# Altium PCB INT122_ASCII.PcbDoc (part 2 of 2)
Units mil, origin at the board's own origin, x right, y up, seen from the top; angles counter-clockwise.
Board outline 4500 x 3260 mil, 4 copper layers (Top Layer, GND Layer, VCC Layer, Bottom Layer), stack 61.6 mil thick; 94 components, 30 nets, 233 pads, 39 vias.
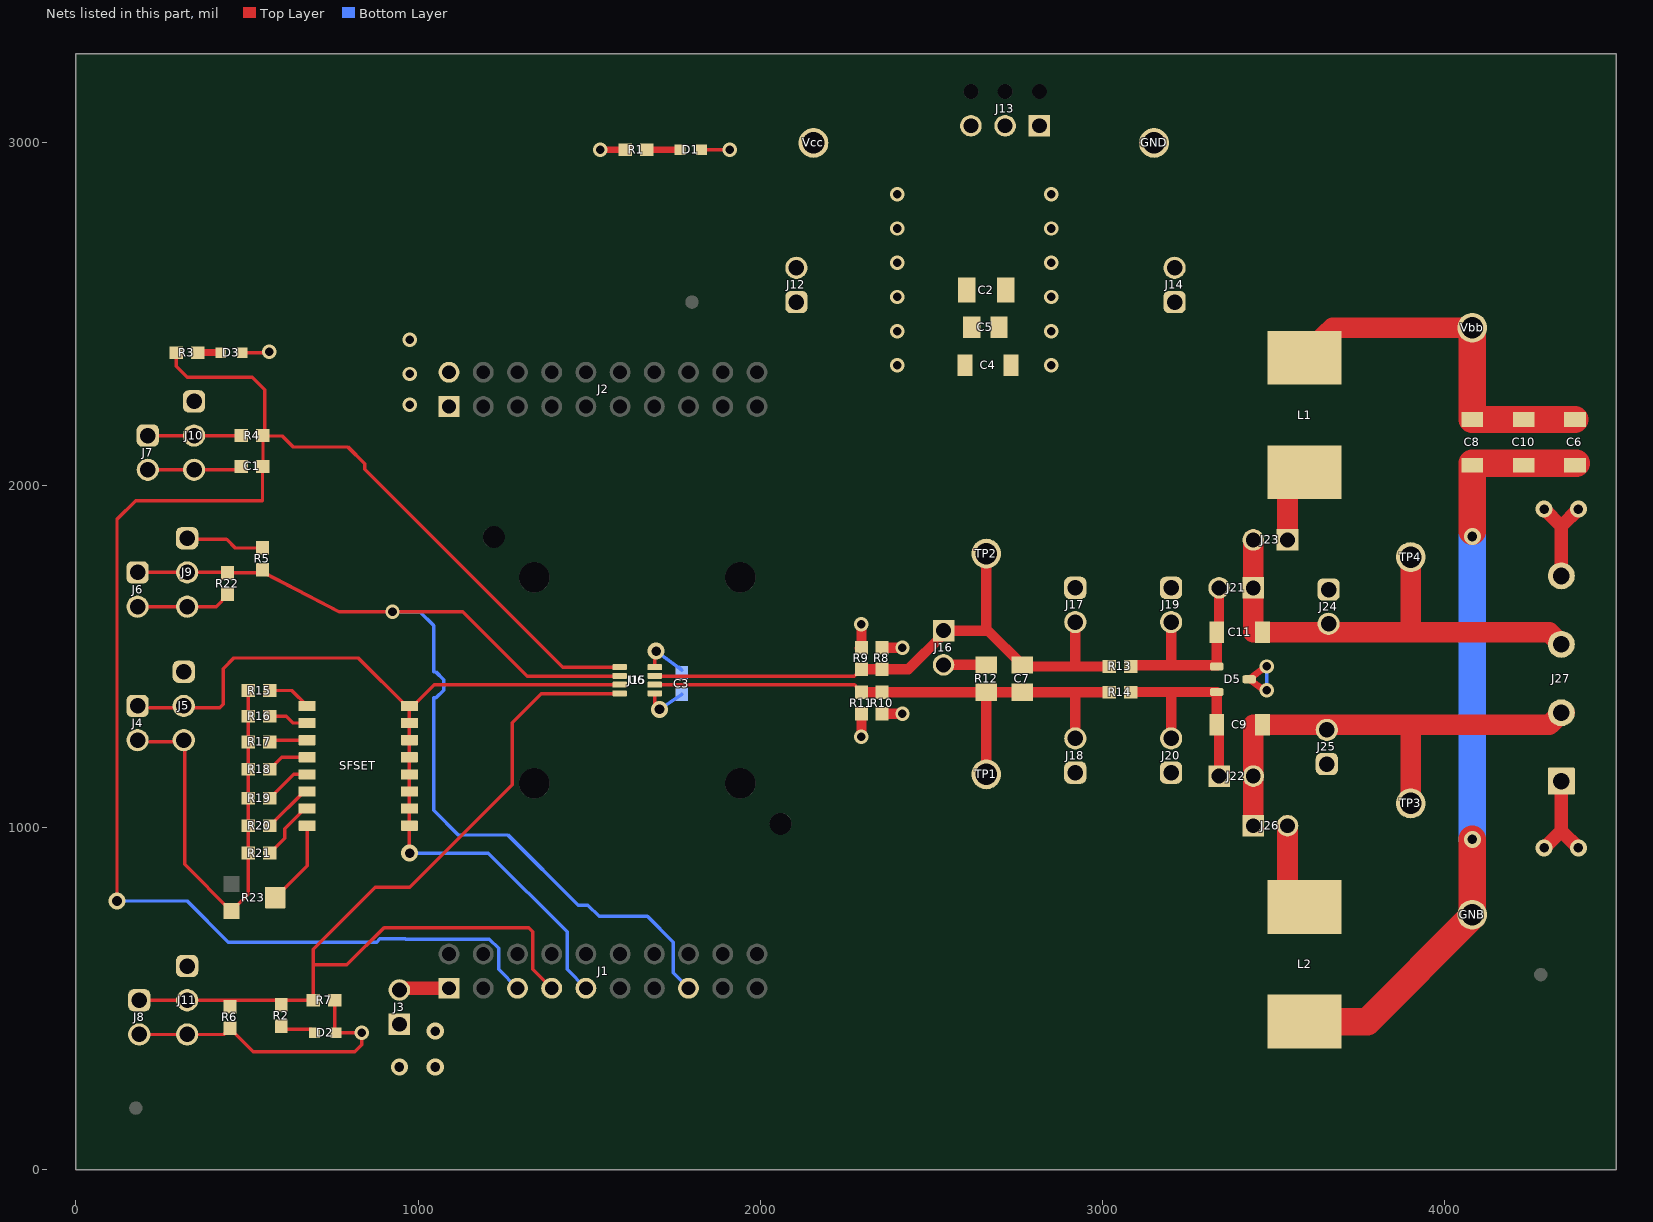
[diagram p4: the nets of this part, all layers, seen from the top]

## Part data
C1: library part CMP-0006767-4, "CAP, CERM, 15 pF, 50 V, +/- 5%, C0G/NP0, 0603"
C2: library part CMP-0008509-2, "CAP, CERM, 1 uF, 25 V, +/- 10%, X7R, 1206"
C3: library part CMP-0085846-1, "CAP, CERM, 0.1 µF, 6.3 V,+/- 10%, X5R, 0603"
C4: library part CMP-0008705-2, "CAP, CERM, 10 uF, 35 V, +/- 10%, X7R, 1206"
C5: library part CMP-0078699-1, "CAP, CERM, 47 µF, 10 V,+/- 20%, X5R, 0805"
C6: library part CMP-0008656-2, "CAP, CERM, 47 uF, 25 V, +/- 20%, X5R, 1206_190"
C7: library part CMP-0007567-2, "CAP, CERM, 0.1 uF, 25 V, +/- 10%, X7R, 0805"
C8 C9 C11: library part CMP-0008779-2, "CAP, CERM, 1 uF, 100 V, +/- 10%, X7R, AEC-Q200 Grade 1, 1206"
C10: library part CMP-0008802-2, "CAP, CERM, 10 uF, 50 V, +/- 10%, X7R, 1206"
D1: library part CMP-0002946-3, "LED, Blue, SMD"
D2: library part CMP-0002905-2, "LED, Green, SMD"
D3: library part CMP-0002947-3, "LED, Red, SMD"
D5: library part CMP-0005918-3, "Diode, TVS, Bi, 12 V, 25.9 Vc, SOT-23"
FID1 FID2 FID3: library part CMP-0077181-1, "Fiducial mark.  There is nothing to buy or mount."
GNB GND: library part CMP-0055148-1, "Test Point, Multipurpose, Black, TH"
H1 H2 H3 H4: library part CMP-0003620-1, "Bumpon, Hemisphere, 0.44 X 0.20, Clear"
J1 J2: library part CMP-0055675-1, "Receptacle, 2.54mm, 10x2, Gold, TH"
J3 J16 J21 J22 J23 J26: library part CMP-0075197-1, "Header, 2.54mm, 2x1, TH"
J4 J6 J7 J8 J12 J14 J17 J18 J19 J20 J24 J25: library part CMP-0054794-2, "Header, 2.54 mm, 2x1, Gold, TH"
J5 J9 J10 J11: library part CMP-0054796-2, "Header, 2.54 mm, 3x1, Gold, TH"
J13: library part CMP-0055500-1, "Terminal Block, 3x1, 2.54 mm, TH"
J15: library part CMP-0088168-1, "CUSTOM SOCKET FOR 1.6X2.9X1.1mm DEVICE, DDF PACKAGE, 0.65mm PITCH, HIGH SPEED SPRING PROBES POGO-1300"
J27: library part CMP-0074939-1, "Terminal Block, 5.08 mm, 4x1, Brass, TH"
L1 L2: library part CMP-0061931-2, "Inductor, Shielded Drum Core, Ferrite, 120 uH, 1.9 A, 0.18 ohm, SMD"
Logo1: library part CMP-0074838-1, "Texas Instrument Corporate Signature"
Logo2: library part CMP-0074844-1
Logo3: library part CMP-0074847-1, "FCC_disclaimer"
Logo4: library part CMP-0074769-1
R1 R2 R3: library part CMP-0025729-4, "RES, 1.0 k, 5%, 0.1 W, AEC-Q200 Grade 0, 0603"
R4 R13 R14: library part CMP-0081973-1, "RES, 0, 0%, 0.25 W, AEC-Q200 Grade 0, 0603"
R5 R7: library part CMP-0025945-3, "RES, 10 k, 5%, 0.1 W, 0603"
R6 R22: library part CMP-0082504-1, "RES, 50, 2%, 3.9 W, 0603"
R8 R11: library part CMP-0025890-5, "RES, 15 k, 5%, 0.1 W, 0603"
R9 R10 R18: library part CMP-0022777-5, "RES, 12.4 k, 1%, 0.1 W, 0603"
R12: library part CMP-0020795-2, "RES, 120, 5%, 0.5 W, 0805"
R15: library part CMP-0022689-3, "RES, 1.50 k, 1%, 0.1 W, 0603"
R16: library part CMP-0022453-4, "RES, 4.42 k, 1%, 0.1 W, AEC-Q200 Grade 0, 0603"
R17: library part CMP-0022666-4, "RES, 9.31 k, 1%, 0.1 W, AEC-Q200 Grade 0, 0603"
R19: library part CMP-0022860-5, "RES, 19.1 k, 1%, 0.1 W, 0603"
R20: library part CMP-0023142-5, "RES, 49.9 k, 1%, 0.1 W, 0603"
R21: library part CMP-0022593-4, "RES, 76.8 k, 1%, 0.1 W, AEC-Q200 Grade 0, 0603"
R23: library part CMP-0065392-2, "TRIMMER 10K OHM 0.1W"
SFSET: library part CMP-0065297-1, "Switch, 8SPST, 0.025 A, 24 VDC, SMD"
SH-J1 SH-J2: library part CMP-0078738-1, "Single Operation 2.54mm Pitch Open Top Jumper Socket"
TP1 TP2 TP3 TP4: library part CMP-0055149-1, "Test Point, Multipurpose, White, TH"
U6: library part CMP-0088703-2, "RS-485 Transceiver with OOK Modulation for Power Line Communication"
Vbb Vcc: library part CMP-0055147-1, "Test Point, Multipurpose, Red, TH"
ZZ1: library part CMP-0003616-3
ZZ2: library part CMP-0077236-1
ZZ3: library part CMP-0077237-1
ZZ4: library part CMP-0077238-1

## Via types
v1: diameter 42, hole 25, Top Layer to Bottom Layer, 26 vias
v2: diameter 50, hole 28, Top Layer to Bottom Layer, 13 vias

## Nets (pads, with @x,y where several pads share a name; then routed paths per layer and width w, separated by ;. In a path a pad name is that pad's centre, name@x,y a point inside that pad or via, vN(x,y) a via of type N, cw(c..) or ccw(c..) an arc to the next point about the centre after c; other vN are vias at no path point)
A: C7.2 J15.6 J18.2 R10.1 R11.2 R12.1 R14.1 TP1.1 U6.6 | length 1689.3
  Top Layer w10: J15.6@1691,1416.3 2274.76,1416.3 R11.2@2283.07,1407.55
  Top Layer w30: R11.2@2295,1395 R10.1@2355,1395 R12.1@2660,1395 ; TP1.1@2660,1155 R12.1@2660,1395 ; C7.2@2760,1395 R12.1@2660,1395 ; C7.2@2765,1395 2920,1395 ; J18.2@2920,1260 2920,1395 ; R14.1@3018.5,1395 2920,1395
A2: C9.2 D5.2 J20.2 J22.1 R14.2 | length 649.3
  Top Layer w10: R14.2@3081.5,1395 R14.2@3081.95,1395.46 ; J22.1@3331.06,1158.94 J22.1@3340,1150
  Top Layer w30: R14.2@3081.95,1395.46 3200,1395.46 ; J20.2@3200,1260 3200,1395.46 ; C9.2@3331.06,1300.3 3340,1291.36 J22.1@3340,1150 ; C9.2@3333.32,1300.3 D5.2@3333.32,1395.46 3200,1395.46
A_LC: C9.1 J22.2 J25.2 J26.1 J27.2 TP3.1 | length 1449.7
  Top Layer w40: J27.2@4340,1335 J27.2@4360,1335
  Top Layer w60: J26.1@3440,1005 J22.2@3440,1150 3440,1300.3 C9.1@3464.92,1300.3 ; C9.1@3475.22,1300.3 3900,1300.3 ; TP3.1@3900,1070 3900,1300.3 ; J27.2@4340,1335 4305.3,1300.3 3900,1300.3
B: C7.1 J15.7 J16.1 J17.2 R8.1 R9.2 R13.1 TP2.1 U6.7 | length 1781.6
  Top Layer w10: J15.7@1691,1441.9 2274.7,1441.9 R9.2@2295,1462.2
  Top Layer w30: R9.2@2295,1462.2 R8.1@2355,1462.2 2432.2,1462.2 2535,1565 J16.1@2535,1575 2665,1575 C7.1@2765,1475 2769.74,1470.26 2920,1470.26 ; 2660,1580 TP2.1@2660,1800 ; J17.2@2920,1600 2920,1470.26 ; R13.1@3018.5,1470.26 2920,1470.26
B2: C11.2 D5.1 J19.2 J21.2 R13.2 | length 607.6
  Top Layer w30: R13.2@3081.94,1474 D5.1@3335,1474 ; 3200,1475 J19.2@3200,1604.74 ; D5.1@3333.32,1478 C11.2@3333.32,1570.3 3340,1576.98 J21.2@3340,1700
B_LC: C11.1 J21.1 J23.2 J24.2 J27.3 TP4.1 | length 1388.8
  Top Layer w60: J23.2@3440,1840 J21.1@3440,1700 3440,1570.3 C11.1@3466.85,1570.3 ; C11.1@3481.55,1570.3 3899.87,1570.3 ; TP4.1@3899.87,1789.5 3899.87,1570.3 ; J27.3@4340,1535 4304.7,1570.3 3899.87,1570.3
D: J1.7 J8.1 J11.2 J15.4 R2.1 R6.2 R7.2 U6.4 | length 2813.5
  Top Layer w10: J8.1@215,495 315,495 565,495 R7.2@690,495 ; R7.2@693.5,495 693.5,598.5 ; J1.7@1390,530 1335,585 1335,695 1322.99,707.01 900,707.01 791.5,598.5 693.5,598.5 ; J15.4@1589,1390.7 1360,1390.7 1275,1305.7 1275,1125 975,825 875,825 693.5,643.5 693.5,598.5
F_SET: J1.9 J4.1 J5.2 J15.3 SFSET.9 SFSET.10 SFSET.11 SFSET.12 SFSET.13 SFSET.14 SFSET.15 SFSET.16 U6.3 | length 2740.8
  Top Layer w10: 215,1350 315,1350 420,1350 430,1360 430,1463.93 461.07,1495 825,1495 965,1355 SFSET.16@974.41,1355 ; v2@974.41,935.59 SFSET.9@974.41,1005 SFSET.10@974.41,1055 SFSET.11@974.41,1105 SFSET.12@974.41,1155 SFSET.13@974.41,1205 SFSET.14@974.41,1255 SFSET.15@974.41,1305 SFSET.16@974.41,1355 ; J15.3@1589,1416.3 1046.3,1416.3 985,1355 SFSET.16@974.41,1355
  Bottom Layer w10: v2(975,925) 1205,925 1435,695 1435,585 J1.9@1490,530
GND_BRD: C1.2 C2.2 C3.1 C4.2 C5.1 D1.1 D2.1 D3.1 D5.3 GND.1 J2.1 J2.2 J4.2 J5.3 J6.2 J7.2 J8.2 J9.3 J10.3 J11.3 J13.1 J13.2 J14.1 J14.2 J15.5 J17.1 J18.1 J19.1 J20.1 J24.1 J25.1 J27.1 R6.1 R7.1 R9.1 R11.1 R15.1 R16.1 R17.1 R18.1 R19.1 R20.1 R21.1 R22.1 R23.3 U6.5 | length 3640.2
  Top Layer w10: J6.2@175,1645 320,1645 409.43,1645 R22.1@442.5,1678.07 ; J8.2@215,395 315,395 431.5,395 R6.1@450,413.5 518.5,345 815,345 835,365 v1(835,400) D2.1@760.2,400 ; 215,1250 315,1250 317.5,1247.5 317.5,892.26 R23.3@454.13,755.63 503.5,805 R21.1@503.5,925 R20.1@503.5,1005 R19.1@503.5,1085 R18.1@503.5,1170 R17.1@503.5,1250 R16.1@503.5,1325 R15.1@503.5,1400 ; J7.2@225,2045 325,2045 C1.2@480.55,2045 ; D3.1@485.94,2387.2 562.2,2387.2 v1(565,2390) ; D2.1@756.5,403.7 R7.1@756.5,495 ; J15.5@1691,1390.7 1691,1359 v2(1705,1345) ; D1.1@1827.99,2980 v1(1910,2980) ; v1@3472.17,1400.3 v1(3479.92,1400.3) ; v1@3477.05,1470.3 v1(3479.92,1470.3)
  Top Layer w20: R9.1@2285,1523.7 R9.1@2295,1533.7 ; v1@3472.17,1400.3 D5.3@3427.81,1432.86 v1@3477.05,1470.3
  Top Layer w30: v1(2295,1265) R11.1@2295,1332.01 ; R9.1@2295,1533.7 v1@2295,1583.7
  Top Layer w40: v2(4290,940) 4340,990 ; J27.1@4350,1125 J27.1@4340,1135 4340,990 ; v2(4390,940) 4340,990
  Bottom Layer w10: v2(1705,1345) C3.1@1770,1388.5 ; v1(3479.92,1400.3) v1(3479.92,1470.3)
  other v1: 2295,1593.7 975,2235 975,2325 2850,2350 975,2425 2850,2450 2850,2550 2850,2650 2850,2750 2850,2850
GND_BUS: C6.1 C8.1 C10.1 GNB.1 L2.2 | length 2232
  Top Layer w10: C6.1@4383.88,2064.19 C6.1@4385,2063.07
  Top Layer w80: L2.2@3590,432.68 3772.68,432.68 4080,740 GNB.1@4080,745 v2(4080,965) ; v2@4080,1865 C8.1@4080,2058.07 4080,2064.19 C6.1@4383.88,2064.19
  Bottom Layer w80: v2(4080,965) v2(4080,1850)
LP_3V3: J1.1 J3.2 | length 151
  Top Layer w40: J3.2@937.58,530 J1.1@1088.58,530
MODE: J1.15 J6.1 J9.2 J15.2 R5.1 R22.2 U6.2 | length 3232
  Top Layer w10: J6.1@180,1745 320,1745 441.5,1745 R22.2@442.5,1744 549,1744 770,1630 v1(925,1630) ; v1@930,1630 1130,1630 1318.1,1441.9 J15.2@1589,1441.9
  Bottom Layer w10: v1(925,1630) 1005,1630 1045,1590 1045,1454.17 1051.99,1454.17 1074.17,1431.99 1074.17,1400.61 1051.99,1378.43 1045,1378.43 1045,1050 1117.13,977.87 1262.4,977.87 1467.4,772.87 1495.69,772.87 1528.56,740 1670,740 1745,665 1745,575 J1.15@1790,530
NetD1_2: D1.2 R1.2 | length 97
  Top Layer w20: R1.2@1667.99,2980 D1.2@1765,2980
NetD2_2: D2.2 R2.2 | length 106.9
  Top Layer w10: R2.2@599.8,418.5 608.31,410 687.2,410 D2.2@697.2,400 ; R2.2@599.8,430.39 R2.2@599.8,432.2
NetD3_2: D3.2 R3.2 | length 67
  Top Layer w20: R3.2@355.94,2387.2 D3.2@422.95,2387.2
NetJ7_1: J7.1 J10.2 R4.1 | length 264
  Top Layer w10: J7.1@225,2145 325,2145 487.2,2145 R4.1@488.5,2143.7
NetJ23_1: J23.1 L1.2 | length 219.9
  Top Layer w60: J23.1@3540,1840 3540,1992.68 L1.2@3590,2037.68
NetJ26_2: J26.2 L2.1 | length 258.4
  Top Layer w60: J26.2@3540,1005 3540,817.32 L2.1@3590,767.32
NetR15_2: R15.2 SFSET.1 | length 127.7
  Top Layer w10: R15.2@566.5,1400 630.59,1400 SFSET.1@675.59,1355
NetR16_2: R16.2 SFSET.2 | length 117.4
  Top Layer w10: R16.2@566.5,1325 615,1325 635,1305 SFSET.2@675.59,1305
NetR17_2: R17.2 SFSET.3 | length 111.2
  Top Layer w10: R17.2@566.5,1250 571.5,1255 SFSET.3@675.59,1255
NetR18_2: R18.2 SFSET.4 | length 123.6
  Top Layer w10: R18.2@566.5,1170 601.5,1205 SFSET.4@675.59,1205
NetR19_2: R19.2 SFSET.5 | length 138.1
  Top Layer w10: R19.2@566.5,1085 636.5,1155 SFSET.5@675.59,1155
NetR20_2: R20.2 SFSET.6 | length 150.5
  Top Layer w10: R20.2@566.5,1005 666.5,1105 SFSET.6@675.59,1105
NetR21_2: R21.2 SFSET.7 | length 179.3
  Top Layer w10: R21.2@566.5,925 610,968.5 610,996.44 668.56,1055 SFSET.7@675.59,1055
NetR23_2: R23.2 SFSET.8 | length 248.7
  Top Layer w10: R23.2@582.09,795 675.59,888.5 SFSET.8@675.59,1005
R: C1.1 J1.5 J15.1 R3.1 R4.2 U6.1 | length 4862
  Top Layer w10: v2(120,785) 120,1900 175,1955 545,1955 546.5,2138.7 R4.2@551.5,2143.7 ; R3.1@292.95,2387.2 292.95,2347.05 325,2315 515,2315 551.5,2278.5 R4.2@551.5,2143.7 ; J15.1@1589,1467.5 1422.5,1467.5 843.5,2046.5 843.5,2062.99 795,2111.5 770,2111.5 635,2111.5 602.8,2143.7 R4.2@551.5,2143.7
  Bottom Layer w10: v2(120,785) 325,785 445,665 878.8,665 888.17,674.37 961.83,674.37 962.81,673.39 1207.97,673.39 1235,646.36 1235,585 J1.5@1290,530
R_term: J16.2 R12.2 | length 125
  Top Layer w30: J16.2@2535,1475 R12.2@2660,1475
VCC_BRD: C2.1 C3.2 C4.1 C5.2 J3.1 J5.1 J9.1 J10.1 J11.1 J12.1 J12.2 J13.3 J15.8 J27.4 R1.1 R5.2 R8.2 R10.2 U6.8 Vcc.1 | length 863.9
  Top Layer w10: J9.1@320,1842.5 440,1842.5 466,1816.5 R5.2@545,1816.5 ; J15.8@1691,1467.5 1691,1511 v2(1695,1515)
  Top Layer w20: v1(1531.5,2980) R1.1@1600,2980
  Top Layer w30: R10.2@2355,1332.01 v1(2415,1332.01) ; R8.2@2355,1525.2 v1(2415,1525.2)
  Top Layer w40: v2(4290,1930) 4340,1880 ; J27.4@4340,1735 4340,1880 ; v2(4390,1930) 4340,1880
  Bottom Layer w10: v2(1695,1515) 1770,1459.77 C3.2@1762.27,1467.5
  other v1: 2400,2350 2400,2450 2400,2550 2400,2650 2400,2750 2400,2850
  other v2: 945,300 1050,300 1050,405
VCC_BUS: C6.2 C8.2 C10.2 L1.1 Vbb.1 | length 1098.4
  Top Layer w10: C6.2@4383.88,2198.05 C6.2@4385,2196.93
  Top Layer w60: L1.1@3580,2372.32 3672.68,2460 Vbb.1@4080,2460
  Top Layer w80: C8.2@4080,2191.93 4180,2191.93 4280,2191.93 C6.2@4380,2191.93 ; C8.2@4080,2198.05 Vbb.1@4080,2460
pads on no net: FID1.1 FID2.1 FID3.1 H1.0 H2.0 H3.0 H4.0 J1.2 J1.3 J1.4 J1.6 J1.8 J1.10 J1.11 J1.12 J1.13 J1.14 J1.16 J1.17 J1.18 J1.19 J1.20 J2.3 J2.4 J2.5 J2.6 J2.7 J2.8 J2.9 J2.10 J2.11 J2.12 J2.13 J2.14 J2.15 J2.16 J2.17 J2.18 J2.19 J2.20 J13.4 J13.5 J13.6 J15. R23.1

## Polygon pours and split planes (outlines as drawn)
VCC_BRD on Top Layer "TOP_LAYER_VCC_BRD_P000" (solid, pour order 0): 2050.01,3260 2647.5,3260 2647.5,2250 2050.01,2250
GND_BRD on Top Layer "TOP_LAYER_GND_BRD_P002" (solid, pour order 2): 3265,3260 2667.5,3260 2667.5,2250 3265,2250
GND_BRD on GND Layer (split plane): 4479.9,20.1 20.1,20.1 20.1,3239.9 4479.9,3239.9
VCC_BRD on VCC Layer (split plane): 4479.9,20.1 20.1,20.1 20.1,3239.9 4479.9,3239.9

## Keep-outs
Keep-Out Layer:
  text ".Layer_Name" at 577,-858.49 h60

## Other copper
Top Layer:
  text ".Layer_Name" at 577,-858.49 h60
Bottom Layer:
  text ".Layer_Name" at 577,-858.49 h60
GND Layer (plane layer: these items are gaps in the copper):
  the board outline again, w40
  text ".Layer_Name" at 577,-858.49 h60
VCC Layer (plane layer: these items are gaps in the copper):
  the board outline again, w40
  text ".Layer_Name" at 577,-858.49 h60

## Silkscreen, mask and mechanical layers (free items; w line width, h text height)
Top Overlay:
  lines w10: 3990,1300 4020,1300 ; 3990,1575 4020,1575 ; 4110,1300 4130,1300 ; 4110,1575 4130,1575
  text "Vcc" at 35,2237.01 h40
  text "GND" at 30,2022.01 h40
  text "Vcc" at 4310,1850 h40
  text "Vcc" at 35,1832.01 h40
  text "GND" at 30,1599.51 h40
  text "B" at 4050,1545 h60
  text "Vcc" at 25,1440.71 h40
  text "A" at 4050,1270 h60
  text "GND" at 30,1212.01 h40
  text "GND" at 4300,985 h40
  text "Vcc" at 20,577.01 h40
  text "R" at 1280,420 h40
  text "D" at 1380,420 h40
  text "MODE" at 1725,410 h40
  text "GND" at 30,372.01 h40
  text "F_SET" at 1425,355 h40
  text ".Layer_Name" at 577,-858.49 h60
Bottom Overlay:
  text ".Layer_Name" at 577,-858.49 h60
Top Paste:
  text ".Layer_Name" at 577,-858.49 h60
Bottom Paste:
  text ".Layer_Name" at 577,-858.49 h60
Top Solder:
  text ".Layer_Name" at 577,-858.49 h60
  text ".Layer_Name" at 577,-858.49 h60
Bottom Solder:
  text ".Layer_Name" at 577,-858.49 h60
Drill Guide:
  text ".Layer_Name" at 577,-858.49 h60
M1 Board Outline:
  the board outline again, w10
  text ".Layer_Name" at 577,-858.49 h60
M2 Board Dimensions:
  rectangle: 125,-400 500,-275
  rectangle: 0,-275 125,-150
  lines w7: 0,-275 1000,-275 ; 125,-400 125,-150 ; 250,-400 250,-150 ; 500,-400 500,-150 ; 750,-400 750,-150 ; 0,-400 0,-150 1000,-150 1000,-400 0,-400
  text ".Layer_Name" at 577,-858.49 h60
M3 3D STEP Top:
  text ".Layer_Name" at 577,-858.49 h60
M4 3D STEP Bottom:
  text ".Layer_Name" at 577,-858.49 h60
M5 Assembly Top:
  lines w10: -292,-930.17 6308,-930.17 ; -292,-726.83 6310,-726.83 ; -292,-523.5 -292,-1133.5 3713,-1133.5 6310,-1133.5 6310,-523.5 -291.5,-523.5 -291.5,-1133.5 1284,-1133.5 ; 2173,-1133.5 2173,-523.5 ; 3440,-726.83 3440,-523.5 ; 4280,-726.83 4280,-523.5 ; 4902,-1140 4902,-937.17
  text "COMPONENTS MARKED 'DNP' SHOULD NOT BE POPULATED." at 1153.5,-318.5 h60
  text "ASSEMBLY VARIANT:" at 1153,-434 h60
  text ".VariantName" at 2189,-434 h60
  text "PCB VIEWED FROM TOP SIDE" at -228.5,-655.67 h60
  text "BOARD #:" at 2248,-655.67 h60
  text ".PRJ_Number" at 2793.5,-655.67 h60
  text "REV:" at 3638,-655.67 h60
  text ".PCB_Rev" at 3929.5,-655.67 h60
  text "SVN REV:" at 4476,-655.67 h60
  text ".VersionControl_RevNumber" at 4982,-655.67 h60
  text "TID #:" at 2248,-859 h60
  text ".TID" at 2793.5,-859 h60
  text "PLOT NAME =" at -228.5,-1064.34 h60
  text ".plot_File_Name" at 577,-1064.34 h60
  text "GENERATED    :" at 2250,-1064.34 h60
  text ".Print_Date" at 3119.5,-1064.34 h60
  text ".Print_Time" at 3848.5,-1064.34 h60
  text "TEXAS INSTRUMENTS" at 5113,-1064.34 h60
M6 Assembly Bottom:
  lines w10: -292.5,-727.33 6309.5,-727.33 ; -290.5,-930.67 6309.5,-930.67 ; 1115.5,-1140.5 1115.5,-937.67 ; 1737.5,-727.33 1737.5,-524 ; 2577.5,-727.33 2577.5,-524 ; 3844.5,-1134 3844.5,-524 ; 4733.5,-1134 6309,-1134 6309,-524 -292.5,-524 -292.5,-1134 2304.5,-1134 6309.5,-1134 6309.5,-524
  text "COMPONENTS MARKED 'DNP' SHOULD NOT BE POPULATED." at 6102,-318 h60
  text ".VariantName" at 5058,-434 h60
  text "ASSEMBLY VARIANT:" at 6097,-434 h60
  text ".VersionControl_RevNumber" at 1035.5,-656.17 h60
  text "SVN REV:" at 1541.5,-656.17 h60
  text ".PCB_Rev" at 2088,-656.17 h60
  text "REV:" at 2379.5,-656.17 h60
  text ".PRJ_Number" at 3224,-656.17 h60
  text "BOARD #:" at 3769.5,-656.17 h60
  text "PCB VIEWED FROM BOTTOM SIDE" at 6246,-656.17 h60
  text ".TID" at 3224,-859.5 h60
  text "TID #:" at 3769.5,-859.5 h60
  text "TEXAS INSTRUMENTS" at 904.5,-1064.84 h60
  text ".Print_Time" at 2169,-1064.84 h60
  text ".Print_Date" at 2898,-1064.84 h60
  text "GENERATED    :" at 3767.5,-1064.84 h60
  text ".plot_File_Name" at 5440.5,-1064.84 h60
  text "PLOT NAME =" at 6246,-1064.84 h60
M9 Title Sheet:
  lines w10: -491.5,1041.5 -291.5,1041.5 ; -491.5,3416.5 -291.5,3416.5 ; -491.5,5791.5 -291.5,5791.5 ; 2008.5,-1333.5 2008.5,-1133.5 ; 2008.5,7966.5 2008.5,8166.5 ; 4508.5,-1333.5 4508.5,-1133.5 ; 4508.5,7966.5 4508.5,8166.5 ; 6321,-1133.5 6321,-523.5 11303.5,-523.5 ; 7008.5,-1333.5 7008.5,-1133.5 ; 7008.5,7966.5 7008.5,8166.5 ; 9508.5,-1333.5 9508.5,-1133.5 ; 9508.5,7966.5 9508.5,8166.5 ; 11303.5,-1133.5 11303.5,-523.5 ; 11303.5,-823.5 14303.5,-823.5 ; 11303.5,-223.5 14303.5,-223.5 ; 11304.5,370.5 14304.5,370.5 ; 12008.5,-1333.5 12008.5,-1133.5 ; 12008.5,7966.5 12008.5,8166.5 ; 12808.5,-1123.5 12808.5,-523.5 ; 14303.5,-523.5 11303.5,-523.5 ; 14303.5,76.5 11303.5,76.5 ; 14308.5,66.5 14308.5,-1133.5 ; 14308.5,871 11304.5,871 11303.5,871 11303.5,370.5 11303.5,76.5 ; 14308.5,1041.5 14508.5,1041.5 ; 14308.5,3416.5 14508.5,3416.5 ; 14308.5,5791.5 14508.5,5791.5 ; 11303.5,-523.5 11303.5,76.5 ; 14308.5,-1133.5 -291.5,-1133.5 -291.5,7966.5 14308.5,7966.5 14308.5,-1133.5 ; -491.5,-1333.5 14508.5,-1333.5 14508.5,8166.5 -491.5,8166.5 -491.5,-1333.5
  text "1" at 739.84,8036.5 h70
  text "2" at 3235.5,8036.5 h70
  text "3" at 5724.84,8036.5 h70
  text "4" at 8231.51,8036.5 h70
  text "5" at 10730.5,8036.5 h70
  text "6" at 13235.5,8036.5 h70
  text "A" at -416.5,6893.5 h70
  text "A" at 14383.5,6893.5 h70
  text "B" at -416.5,4513.5 h70
  text "B" at 14383.5,4513.5 h70
  text "C" at -416.5,2138.5 h70
  text "C" at 14383.5,2138.5 h70
  text "PROJECT TITLE:" at 11343.5,277.5 h45
  text ".PRJ_Title" at 11393.5,144.17 h70
  text "DESIGNED FOR:" at 11343.5,-23.5 h45
  text ".PRJ_Customer" at 11393.5,-163.5 h70
  text "D" at -416.5,-231.5 h70
  text "D" at 14383.5,-231.5 h70
  text "FILE NAME:" at 11343.5,-323.5 h45
  text ".PCB_File_Name_No_Path" at 11393.5,-443.5 h70
  text "Texas Instruments (TI) and/or its licensors do not warrant the accuracy or completeness of this specification" at 6374,-605.34 h45
  text "ENGINEER:" at 11343.5,-613.5 h45
  text "LAYOUT BY:" at 12848.5,-613.5 h45
  text "or any information contained therein. TI and/or its licensors do not warrant that this design will meet" at 6329.01,-718 h45
  text ".PRJ_Engineer" at 11393.5,-768.49 h70
  text ".PCB_Layout" at 12899,-768.49 h70
  text "the specifications, will be suitable for your application or fit for any particular purpose, or will operate in" at 6329.01,-830.67 h45
  text ".Layer_Name" at 577,-858.49 h60
  text "ALTIUM DESIGNER VERSION:" at 12848.5,-923.5 h45
  text "an implementation. TI and/or its licensors do not warrant that the design is production worthy. You should" at 6329.01,-943.33 h45
  text "completely validate and test your design implementation to confirm the system functionality for your application." at 6374,-1056 h45
  text ".print_Scale" at 11393.5,-1056.83 h70
  text ".Application_BuildNumber" at 12899,-1056.83 h70
  text "1" at 739.84,-1263.5 h70
  text "2" at 3235.5,-1263.5 h70
  text "3" at 5724.84,-1263.5 h70
  text "4" at 8231.51,-1263.5 h70
  text "5" at 10730.5,-1263.5 h70
  text "6" at 13235.5,-1263.5 h70
M10 Fab Notes:
  drawing of 189 lines, arcs and shapes, not listed
  text "DESIGN INFORMATION" at 12382.02,6356.17 h60
  text "MIN. TRACK WIDTH:" at 11737.46,6224.05 h60
  text "8" at 12833.7,6224.05 h60
  text "MIL" at 12988.46,6224.05 h60
  text "MIN. CLEARANCE:" at 11737.46,6099.92 h60
  text "0.2" at 12773.7,6099.93 h60
  text "mm" at 12988.46,6099.92 h60
  text "MIN. VIA PAD SIZE:" at 11737.46,5975.8 h60
  text "24" at 12803.71,5975.8 h60
  text "MIL" at 12988.46,5975.8 h60
  text "0.05mm (2MIL)" at 12432.46,5845.9 h60
  text "MINIMUM ANNULAR RING" at 11408.23,5837.67 h60
  text "EXTERNAL" at 13140.46,5837.67 h60
  text "PER" at 11608.23,5727.55 h60
  text "IPC-D-275 CLASS 2 LEVEL C" at 11828.23,5727.54 h60
  text "MIL, HOLES" at 13316.46,5627.07 h60
  text "+/-" at 12924,5618.48 h60
  text "+/-" at 13778,5618.48 h60
  text "REGISTRATION TOLERANCES:" at 11408.23,5617.42 h60
  text "METAL" at 12608,5617.42 h60
  text "5" at 13184.2,5617.42 h60
  text "3" at 14017.2,5617.42 h60
  text "MIL" at 14133.46,5617.42 h60
  text "HOLE SIZE TOLERANCE (UNLESS OTHERWISE SPECIFIED):" at 11408.23,5519.1 h60
  text "+/-" at 13778,5516.23 h60
  text "3" at 14017.2,5515.17 h60
  text "MIL" at 14133.46,5515.17 h60
  text "MATERIAL:" at 11333.46,5377.52 h60
  text "FR-4 High Tg" at 12319.9,5249 h60
  text "X" at 12175.46,5241.01 h60
  text "FR-408" at 11754.46,5236.49 h60
  text "OTHER" at 13242.46,5236.49 h60
  text "62 MIL (1.6mm) +/-10%" at 12074.56,5093.46 h60
  text "X" at 11954.46,5091.01 h60
  text "THICKNESS:" at 11408.23,5085.24 h60
  text "OTHER" at 13359.46,5085.24 h60
  text "TOLERANCE:" at 11408.23,4946.92 h60
  text "X" at 12256.46,4946.92 h60
  text "ANSI IPC-6012 TYPE 3 CLASS 2" at 12434.48,4946.92 h60
  text "OTHER +/-" at 12434.46,4802.73 h60
  text "BOW & TWIST:" at 11408.23,4657.54 h60
  text "X" at 12256.46,4657.54 h60
  text "ANSI IPC-6012 TYPE 3 CLASS 2" at 12434.48,4657.54 h60
  text "OTHER +/-" at 12434.46,4510.85 h60
  text "DRILLING:" at 11333.46,4380.23 h60
  text "NC_DRILL FILES" at 13094.46,4275.04 h60
  text "REFERENCE:" at 11408.23,4271.1 h60
  text "X" at 12065.46,4271.01 h60
  text "AS SHOWN" at 12243.46,4271.1 h60
  text "X" at 12966.46,4271.1 h60
  text "OTHER" at 13392.46,4128.85 h60
  text "PTH COPPER THICKNESS:" at 11407.91,4125.32 h60
  text "X" at 12547.14,4125.32 h60
  text "20-30 um" at 12675.14,4125.32 h60
  text "BOARD FINISH:" at 11333.46,3977.73 h60
  text "SILKSCREEN:" at 11488.68,3867.6 h60
  text "X" at 12446.46,3867.6 h60
  text "TOP" at 12563.46,3867.6 h60
  text "X" at 12956.46,3867.6 h60
  text "BOTTOM" at 13074.46,3867.6 h60
  text "SILKSCREEN COLOR:" at 11488.68,3712.41 h60
  text "X" at 12445.46,3712.41 h60
  text "WHITE" at 12563.46,3712.41 h60
  text "OTHER" at 13074.46,3712.41 h60
  text "X" at 12576.46,3568.96 h60
  text "GREEN" at 12694.46,3568.96 h60
  text "OTHER" at 13312.46,3568.96 h60
  text "SOLDER RESIST COLOR:" at 11488.68,3562.1 h60
  text "X" at 12576.46,3414.71 h60
  text "MATTE" at 12694.46,3414.71 h60
  text "SEMI-GLOSS" at 13312,3414.07 h60
  text "IMMERSION GOLD (ENIG)" at 12394.46,3241.94 h60
  text "ENEPIG" at 13732,3234.72 h60
  text "SURFACE FINISH:" at 11333.46,3233.72 h60
  text "X" at 12216.46,3233.72 h60
  text "IMM. TIN/SILVER OR EQUIV" at 11663,3096.4 h60
  text "OTHER" at 13094.46,3092.47 h60
  text "ARRAY/PANEL:" at 11333.46,2937.09 h60
  text "CUT AND TRIM PER M1 BOARD OUTLINE" at 12394.46,2928.87 h60
  text "N.C. ROUTE" at 12394.46,2792.9 h60
  text "X" at 13082.46,2792.9 h60
  text "V. SCORE" at 13260.46,2792.9 h60
  text "CERTIFICATION:" at 11333.46,2663.77 h60
  text "MATERIALS AND WORKMANSHIP FOR ALL PCBS" at 12058.46,2663.77 h60
  text "TO MEET OR EXCEED THE REQUIREMENTS OF:" at 12058.46,2569.71 h60
  text "X" at 11695.97,2441.08 h60
  text "ANSI IPC-A-600F CLASS ->" at 11823.96,2441.08 h60
  text "X" at 13471.97,2441.08 h60
  text "2" at 13581.96,2441.08 h60
  text "1" at 13266.96,2439.58 h60
  text "3" at 13935.96,2439.58 h60
  text "X" at 12507.97,2293.39 h60
  text "RoHS" at 12635.96,2293.39 h60
  text "OTHER" at 13280.36,2293.39 h60
  text "PER ORDER" at 13677.42,2293.39 h60
  text "ALL BOARDS MUST MEET OR EXCEED UL94-V0 REQUIREMENTS." at 11361,2139.57 h60
  text "PCB MUST BEAR THE UL94V-0 UL REGISTERED MATERIAL ID NUMBER" at 11361,2023.5 h60
  text "ADDITIONAL REQUIREMENTS:" at 11333.46,1854.08 h60
  text "MICROSECTION:" at 11408.23,1746.95 h60
  text "YES" at 12313.96,1746.95 h60
  text "REQUIRED" at 13175.46,1602.62 h60
  text "BARE BOARD ELEC. TEST:" at 11408.23,1599.76 h60
  text "NONE" at 12713.96,1599.76 h60
  text "X" at 13057.46,1599.76 h60
  text "PER ORDER" at 13767.46,1599.76 h60
  text "XX MIL VIAS REQUIRE NON-CONDUCTIVE FILL AND PLANARIZE" at 11576.38,1394.82 h59
  text "XX MIL VIAS REQUIRE CONDUCTIVE FILL AND PLANARIZE" at 11584.38,1290.84 h60
  text "OUTER XX MIL TRACES REQUIRE 50 OHM SINGLE-ENDED IMPEDANCE" at 11583.39,1127.46 h58
  text "LAYER 2 & 3 (INNER LAYERS) XX MIL WIDE, XX MIL SPACE / TRACES REQUIRE 100 OHM DIFFERENTIAL IMPEDANCE" at 11575.39,891.74 h60
  text ".Layer_Name" at 577,-858.49 h60
M11 Gerber Information:
  lines w10: -292,-930.17 6308,-930.17 ; -292,-726.83 6310,-726.83 ; -292,-523.5 -292,-1133.5 3713,-1133.5 6310,-1133.5 6310,-523.5 -291.5,-523.5 -291.5,-1133.5 1284,-1133.5 ; 2173,-1133.5 2173,-523.5 ; 3440,-726.83 3440,-523.5 ; 4280,-726.83 4280,-523.5 ; 4902,-1140 4902,-937.17
  text "ALL ARTWORK VIEWED FROM TOP SIDE" at -228.5,-655.67 h60
  text "BOARD #:" at 2248,-655.67 h60
  text ".PRJ_Number" at 2793.5,-655.67 h60
  text "REV:" at 3638,-655.67 h60
  text ".PCB_Rev" at 3929.5,-655.67 h60
  text "SVN REV:" at 4476,-655.67 h60
  text ".VersionControl_RevNumber" at 4982,-655.67 h60
  text "LAYER NAME =" at -228.5,-858.49 h60
  text "TID #:" at 2248,-859 h60
  text ".TID" at 2793.5,-859 h60
  text "PLOT NAME =" at -228.5,-1064.34 h60
  text ".plot_File_Name" at 577,-1064.34 h60
  text "GENERATED    :" at 2250,-1064.34 h60
  text ".Print_Date" at 3119.5,-1064.34 h60
  text ".Print_Time" at 3848.5,-1064.34 h60
  text "TEXAS INSTRUMENTS" at 5113,-1064.34 h60
M12 Stackup:
  drawing of 295 lines, arcs and shapes, not listed
  text "Layer" at 9797.84,7785 h60
  text "Name" at 10207.76,7785 h60
  text "Material" at 11137.5,7785 h60
  text "Thickness" at 11997.27,7785 h60
  text "Constant" at 12647.1,7785 h60
  text "Board Layer Stack" at 13216.96,7785 h60
  text "1" at 9797.84,7665 h60
  text "Top Overlay" at 10207.76,7665 h60
  text "2" at 9797.84,7545 h60
  text "Top Solder" at 10207.76,7545 h60
  text "Solder Resist" at 11137.5,7545 h60
  text "0.40mil" at 11997.27,7545 h60
  text "3.5" at 12647.1,7545 h60
  text "3" at 9797.84,7425 h60
  text "Top Layer" at 10207.76,7425 h60
  text "Copper" at 11137.5,7425 h60
  text "1.40mil" at 11997.27,7425 h60
  text "4" at 9797.84,7305 h60
  text "Dielectric 1" at 10207.76,7305 h60
  text "FR-4" at 11137.5,7305 h60
  text "8.00mil" at 11997.27,7305 h60
  text "4.2" at 12647.1,7305 h60
  text "5" at 9797.84,7185 h60
  text "GND Layer" at 10207.76,7185 h60
  text "Copper" at 11137.5,7185 h60
  text "1.40mil" at 11997.27,7185 h60
  text "6" at 9797.84,7065 h60
  text "Dielectric 2" at 10207.76,7065 h60
  text "FR-4" at 11137.5,7065 h60
  text "40.00mil" at 11997.27,7065 h60
  text "4.2" at 12647.1,7065 h60
  text "7" at 9797.84,6945 h60
  text "VCC Layer" at 10207.76,6945 h60
  text "Copper" at 11137.5,6945 h60
  text "1.40mil" at 11997.27,6945 h60
  text "8" at 9797.84,6825 h60
  text "Dielectric 3" at 10207.76,6825 h60
  text "FR-4" at 11137.5,6825 h60
  text "8.00mil" at 11997.27,6825 h60
  text "4.2" at 12647.1,6825 h60
  text "9" at 9797.84,6705 h60
  text "Bottom Layer" at 10207.76,6705 h60
  text "Copper" at 11137.5,6705 h60
  text "1.40mil" at 11997.27,6705 h60
  text "10" at 9797.84,6585 h60
  text "Bottom Solder" at 10207.76,6585 h60
  text "Solder Resist" at 11137.5,6585 h60
  text "0.40mil" at 11997.27,6585 h60
  text "3.5" at 12647.1,6585 h60
  text "11" at 9797.84,6465 h60
  text "Bottom Overlay" at 10207.76,6465 h60
  text ".Layer_Name" at 577,-858.49 h60
M13 Component Bodies Top:
  text ".Layer_Name" at 577,-858.49 h60
M14 Component Bodies Bottom:
  text ".Layer_Name" at 577,-858.49 h60
M15 Courtyards Top:
  text ".Layer_Name" at 577,-858.49 h60
M16 Courtyards Bottom:
  text ".Layer_Name" at 577,-858.49 h60
Drill Drawing:
  circle w10: c5348.9,2816.67 r13.28
  circle w10: c5348.9,2816.67 r22.14
  circle w10: c5348.9,2517.8 r22.14
  lines w10: 5326.76,2440.32 5371.04,2440.32 5348.9,2396.04 5326.76,2440.32 ; 5326.76,2606.35 5337.83,2606.35 5348.9,2595.29 5359.97,2606.35 5371.04,2606.35 5359.97,2617.42 5371.04,2628.49 5359.97,2628.49 5348.9,2639.56 5337.83,2628.49 5326.76,2628.49 5337.83,2617.42 5326.76,2606.35 ; 5326.76,2694.91 5326.76,2705.98 5337.83,2717.05 5326.76,2728.11 5326.76,2739.18 5337.83,2739.18 5348.9,2728.11 5359.97,2739.18 5371.04,2739.18 5371.04,2728.11 5359.97,2717.05 5371.04,2705.98 5371.04,2694.91 5359.97,2694.91 5348.9,2705.98 5337.83,2694.91 5326.76,2694.91 ; 5326.76,2894.15 5371.04,2894.15 5371.04,2938.43 5326.76,2938.43 5326.76,2894.15 ; 5326.76,2993.77 5371.04,2993.77 5371.04,3038.05 5326.76,3038.05 5326.76,2993.77 ; 5326.76,3137.67 5371.04,3137.67 5348.9,3093.4 5326.76,3137.67 ; 5326.76,3204.09 5337.83,3204.09 5348.9,3193.02 5359.97,3204.09 5371.04,3204.09 5359.97,3215.16 5371.04,3226.23 5359.97,3226.23 5348.9,3237.3 5337.83,3226.23 5326.76,3226.23 5337.83,3215.16 5326.76,3204.09 ; 5326.76,3314.78 5348.9,3292.64 5371.04,3314.78 5348.9,3336.92 5326.76,3314.78 ; 5335.62,3002.63 5362.18,3002.63 5362.18,3029.2 5335.62,3029.2 5335.62,3002.63 ; 5335.62,3128.82 5362.18,3128.82 5348.9,3102.25 5335.62,3128.82 ; 5335.62,3208.52 5342.26,3208.52 5348.9,3201.87 5355.54,3208.52 5362.18,3208.52 5355.54,3215.16 5362.18,3221.8 5355.54,3221.8 5348.9,3228.44 5342.26,3221.8 5335.62,3221.8 5342.26,3215.16 5335.62,3208.52
  lines w12: 5286,2366.15 8398.94,2366.15 ; 5286,3362.38 8398.94,3362.38 ; 5601.63,2266.53 5601.63,3462 ; 5918.82,2266.53 5918.82,3462 ; 6540.56,2266.53 6540.56,3462 ; 6784.88,2266.53 6784.88,3462 ; 7145.22,2266.53 7145.22,3462 ; 7854.73,2266.53 7854.73,3462 ; 5286,2266.53 8398.94,2266.53 8398.94,3462 5286,3462 5286,2266.53
  text "Symbol" at 5345.77,3392.26 h72
  text "Quantity" at 5631.52,3392.26 h72
  text "Finished Hole Size" at 5948.7,3392.26 h72
  text "Plated" at 6570.45,3392.26 h72
  text "Hole Type" at 6814.77,3392.26 h72
  text "Drill Layer Pair" at 7175.11,3392.26 h72
  text "Hole Tolerance" at 7884.62,3392.26 h72
  text "3" at 5631.52,3292.64 h60
  text "43.31mil (1.100mm)" at 5948.7,3292.64 h60
  text "NPTH" at 6570.45,3292.64 h60
  text "Round" at 6814.77,3292.64 h60
  text "Top Layer - Bottom Layer" at 7175.11,3292.64 h60
  text "2" at 5631.52,3193.02 h60
  text "64.00mil (1.626mm)" at 5948.7,3193.02 h60
  text "NPTH" at 6570.45,3193.02 h60
  text "Round" at 6814.77,3193.02 h60
  text "Top Layer - Bottom Layer" at 7175.11,3193.02 h60
  text "4" at 5631.52,3093.4 h60
  text "89.00mil (2.261mm)" at 5948.7,3093.4 h60
  text "NPTH" at 6570.45,3093.4 h60
  text "Round" at 6814.77,3093.4 h60
  text "Top Layer - Bottom Layer" at 7175.11,3093.4 h60
  text "26" at 5631.52,2993.77 h60
  text "25.00mil (0.635mm)" at 5948.7,2993.77 h60
  text "PTH" at 6570.45,2993.77 h60
  text "Round" at 6814.77,2993.77 h60
  text "Top Layer - Bottom Layer" at 7175.11,2993.77 h60
  text "13" at 5631.52,2894.15 h60
  text "28.00mil (0.711mm)" at 5948.7,2894.15 h60
  text "PTH" at 6570.45,2894.15 h60
  text "Round" at 6814.77,2894.15 h60
  text "Top Layer - Bottom Layer" at 7175.11,2894.15 h60
  text "40" at 5631.52,2794.53 h60
  text "40.16mil (1.020mm)" at 5948.7,2794.53 h60
  text "PTH" at 6570.45,2794.53 h60
  text "Round" at 6814.77,2794.53 h60
  text "Top Layer - Bottom Layer" at 7175.11,2794.53 h60
  text "15" at 5631.52,2694.91 h60
  text "43.31mil (1.100mm)" at 5948.7,2694.91 h60
  text "PTH" at 6570.45,2694.91 h60
  text "Round" at 6814.77,2694.91 h60
  text "Top Layer - Bottom Layer" at 7175.11,2694.91 h60
  text "36" at 5631.52,2595.29 h60
  text "45.28mil (1.150mm)" at 5948.7,2595.29 h60
  text "PTH" at 6570.45,2595.29 h60
  text "Round" at 6814.77,2595.29 h60
  text "Top Layer - Bottom Layer" at 7175.11,2595.29 h60
  text "4" at 5631.52,2495.66 h60
  text "49.21mil (1.250mm)" at 5948.7,2495.66 h60
  text "PTH" at 6570.45,2495.66 h60
  text "Round" at 6814.77,2495.66 h60
  text "Top Layer - Bottom Layer" at 7175.11,2495.66 h60
  text "8" at 5631.52,2396.04 h60
  text "63.00mil (1.600mm)" at 5948.7,2396.04 h60
  text "PTH" at 6570.45,2396.04 h60
  text "Round" at 6814.77,2396.04 h60
  text "Top Layer - Bottom Layer" at 7175.11,2396.04 h60
  text "151 Total" at 5631.52,2296.42 h60
  text ".Layer_Name" at 577,-858.49 h60
Mechanical 17:
  text ".Layer_Name" at 577,-858.49 h60
Mechanical 18:
  text ".Layer_Name" at 577,-858.49 h60
Mechanical 19:
  text ".Layer_Name" at 577,-858.49 h60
